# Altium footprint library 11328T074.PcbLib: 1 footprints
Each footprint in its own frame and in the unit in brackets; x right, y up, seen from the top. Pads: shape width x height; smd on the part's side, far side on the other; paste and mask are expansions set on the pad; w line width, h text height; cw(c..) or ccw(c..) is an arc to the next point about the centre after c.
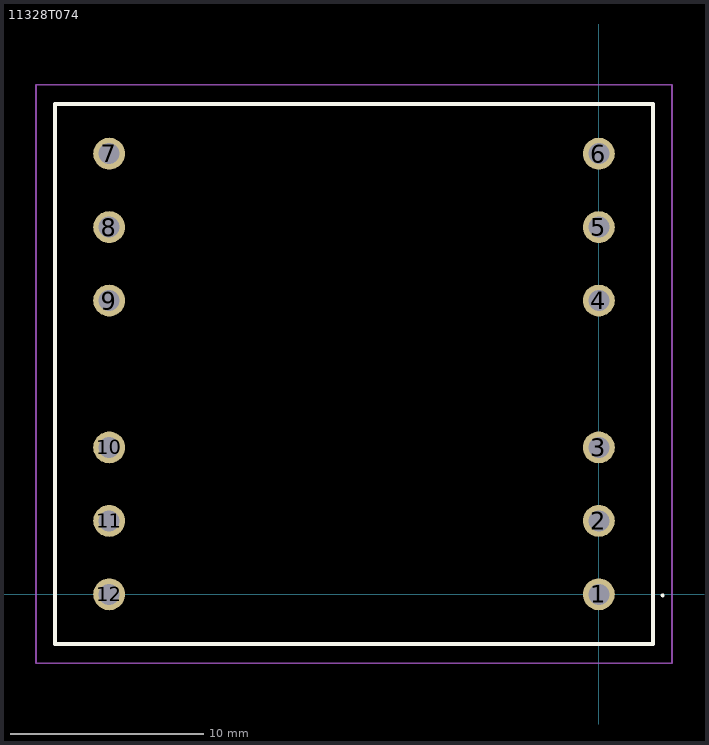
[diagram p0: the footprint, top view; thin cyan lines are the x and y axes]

## 11328T074 [mm]
pads (12):
  round 1.65 hole 1.1: 1(0,0) 2(0,3.81) 3(0,7.62) 4(0,15.24) 5(0,19.05) 6(0,22.86) 7(-25.4,22.86) 8(-25.4,19.05) 9(-25.4,15.24) 10(-25.4,7.62) 11(-25.4,3.81) 12(-25.4,0)
Top Overlay:
  lines w0.1: 3.3,-0.1 3.3,-0.1 ; 3.3,-0.1 ccw(c3.3,-0.049) 3.3,0.002 ; 3.3,-0.1 cw(c3.3,-0.049) 3.3,0.002 ; 3.3,0.002 3.3,0.002
  lines w0.2: -28.2,-2.57 2.8,-2.57 2.8,25.43 -28.2,25.43 -28.2,-2.57
Mechanical 15:
  lines w0.1: -28.2,-2.57 2.8,-2.57 2.8,25.43 -28.2,25.43 -28.2,-2.57
Mechanical 20:
  lines w0.1: -29.2,-3.57 3.8,-3.57 3.8,26.43 -29.2,26.43 -29.2,-3.57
